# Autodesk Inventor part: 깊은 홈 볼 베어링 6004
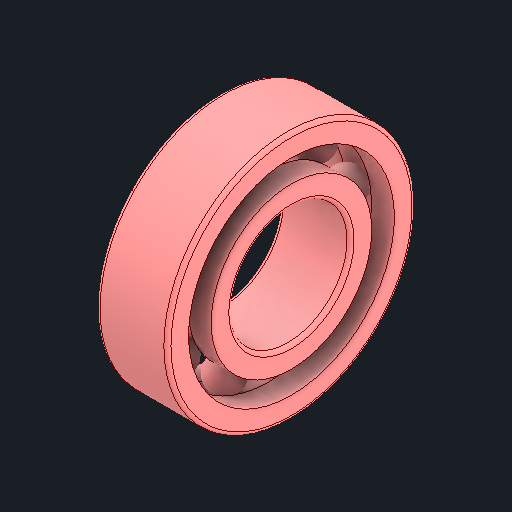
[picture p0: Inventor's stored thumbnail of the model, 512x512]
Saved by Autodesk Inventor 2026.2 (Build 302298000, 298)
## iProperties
Created: 2025-11
Part Number: 깊은 홈 볼 베어링 6004
Material: 강철, 연강
Description: 깊은 그루브 볼 베어링
Document SubType Name: Modeling
Designer: PC2-07
Density: 7.85 g/cm^3
Appearance: 기본값
Author: jhkim
Sending System: Autodesk Inventor 2026
Preprocessor: ST-DEVELOPER v20.1
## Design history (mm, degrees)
feature "Solid1"
feature "Solid1:1"
feature "Solid1:2"
feature "Solid1:3"
feature "Solid1:4"
feature "Solid1:5"
feature "Solid1:6"
feature "Solid1:7"
feature "Solid1:8"
feature "Solid1:9"
feature "Solid1:10"
node "솔리드1"
node "솔리드2"
node "솔리드3"
node "솔리드4"
node "솔리드5"
node "솔리드6"
node "솔리드7"
node "솔리드8"
node "솔리드9"
node "솔리드10"
node "솔리드11"
